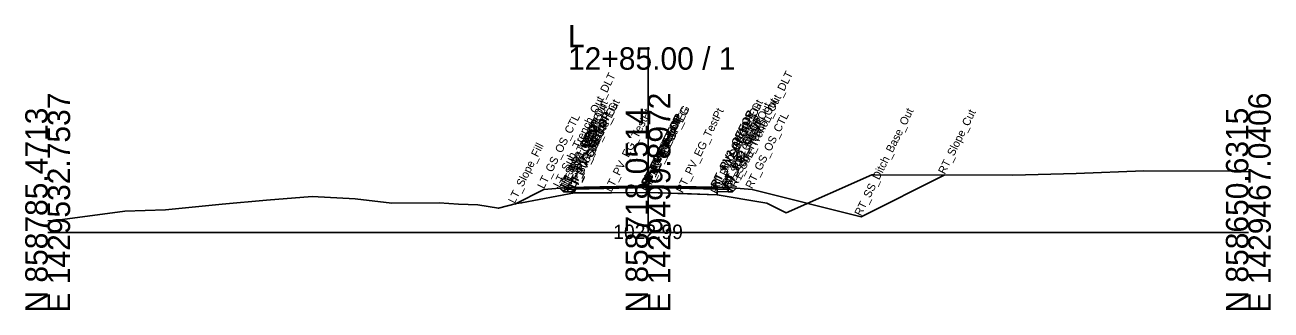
# Model space of a CAD drawing. Extents: x -26 to 2303, y -10 to 19558.
# Drawn here: x 1147.2 to 1302.8, y 4990.3 to 5025.9 of the extents above; entities that cross this region are included whole.
import ezdxf

# ---------------------------------------------------------------- set-up
doc = ezdxf.new("R2010")
doc.units = 0
for name, color, linetype in [('Default', 7, 'Continuous'), ('Exist CMT Pavement', 7, 'Continuous'), ('Exist Cross Section Cell', 7, 'Continuous'), ('Exist XS Center Line Elevation Label', 7, 'Continuous'), ('Exist XS Ground Line', 7, 'Continuous'), ('Prop CMT Conc Surface', 7, 'Continuous'), ('Prop CMT Pvmt Course 1', 7, 'Continuous'), ('Prop CMT Pvmt Course 1 Wedge', 7, 'Continuous'), ('Prop CMT Pvmt Course 2', 7, 'Continuous'), ('Prop CMT Pvmt Course 2 Wedge', 7, 'Continuous'), ('Prop CMT Pvmt Surface', 7, 'Continuous'), ('Prop CMT Pvmt Surface Shoulder', 7, 'Continuous'), ('Prop CMT Pvmt Wedge Surface 1', 7, 'Continuous'), ('Prop CMT Pvmt Wedge Surface 2', 7, 'Continuous'), ('Prop CMT Shld Paved Course 1', 7, 'Continuous'), ('Prop CMT Shld Paved Course 2', 7, 'Continuous'), ('Prop CMT Slope Grass', 7, 'Continuous'), ('Prop CMT Subgrade Earthwork', 7, 'Continuous'), ('Prop XS Dump Level', 7, 'Continuous')]:
    doc.layers.add(name, color=color, linetype=linetype)

msp = doc.modelspace()

# ---------------------------------------------------------------- linework, layer by layer
at = {"layer": 'Exist CMT Pavement'}
for points in [[(1225, 5004.99), (1215.83, 5004.95)], [(1215.83, 5004.95), (1220.42, 5004.98)], [(1220.42, 5004.98), (1225, 5004.99)], [(1229.33, 5004.86), (1225, 5004.99)], [(1225, 5004.99), (1233.66, 5004.72)], [(1233.66, 5004.72), (1229.33, 5004.86)]]:
    msp.add_lwpolyline(points, dxfattribs=at)
at = {"layer": 'Exist Cross Section Cell'}
for p, q in [((1225, 5000), (1225, 5023.15)), ((1150, 5000), (1225, 5000)), ((1225, 5000), (1300, 5000))]:
    msp.add_line(p, q, dxfattribs=at)
at = {"layer": 'Exist XS Ground Line'}
msp.add_lwpolyline([(1150, 5001.48), (1151.22, 5001.54), (1159.64, 5002.66), (1164.71, 5002.84), (1171.81, 5003.54), (1177.34, 5004.03), (1183.06, 5004.5), (1188.4, 5004.23), (1193, 5003.66), (1198.9, 5003.71), (1201.31, 5003.56), (1203.74, 5003.48), (1206.31, 5003.03), (1208.56, 5003.62), (1209.21, 5003.7), (1215.83, 5004.95), (1220.21, 5004.97), (1224.69, 5005), (1225, 5004.99), (1229.19, 5004.86), (1233.66, 5004.72), (1239.36, 5003.77), (1239.84, 5003.69), (1240.16, 5003.5), (1242.28, 5002.48), (1252.96, 5007.21), (1253.34, 5007.23), (1270.59, 5007.19), (1278.49, 5007.37), (1286.93, 5007.72), (1298.54, 5007.65), (1300, 5007.59)], dxfattribs=at)
at = {"layer": 'Prop CMT Conc Surface'}
for p, q in [((1215.83, 5005.1), (1215.83, 5004.95)), ((1233.66, 5004.72), (1233.66, 5005.11))]:
    msp.add_line(p, q, dxfattribs=at)
at = {"layer": 'Prop CMT Pvmt Course 1'}
for points in [[(1225, 5005.83), (1215, 5005.63)], [(1215, 5005.63), (1215, 5005.42)], [(1215, 5005.42), (1215.83, 5005.43)], [(1215.83, 5005.52), (1225, 5005.7)], [(1215.83, 5005.43), (1215.83, 5005.52)], [(1225, 5005.62), (1225, 5005.83)], [(1225, 5005.83), (1235, 5005.63)], [(1225, 5005.62), (1225, 5005.83)], [(1225, 5005.7), (1225, 5005.62), (1225, 5005.62)], [(1233.66, 5005.53), (1225, 5005.7)], [(1225, 5005.7), (1225, 5005.62), (1225, 5005.62)], [(1233.66, 5005.44), (1233.66, 5005.53)], [(1235, 5005.42), (1233.66, 5005.44)], [(1235, 5005.63), (1235, 5005.42)]]:
    msp.add_lwpolyline(points, dxfattribs=at)
at = {"layer": 'Prop CMT Pvmt Course 1 Wedge'}
for points in [[(1225, 5005.7), (1215.83, 5005.52)], [(1225, 5005.7), (1233.66, 5005.53)]]:
    msp.add_lwpolyline(points, dxfattribs=at)
at = {"layer": 'Prop CMT Pvmt Course 2'}
for points in [[(1215.83, 5005.43), (1215, 5005.42)], [(1215, 5005.42), (1215, 5005.08)], [(1215.83, 5005.1), (1215.83, 5005.43)], [(1233.66, 5005.11), (1233.66, 5005.44)], [(1233.66, 5005.44), (1235, 5005.42)], [(1235, 5005.42), (1235, 5005.08)], [(1215, 5005.08), (1215.83, 5005.1)], [(1235, 5005.08), (1233.66, 5005.11)]]:
    msp.add_lwpolyline(points, dxfattribs=at)
at = {"layer": 'Prop CMT Pvmt Course 2 Wedge'}
for points in [[(1225, 5005.62), (1215.83, 5005.43)], [(1225, 5005.62), (1233.66, 5005.44)]]:
    msp.add_lwpolyline(points, dxfattribs=at)
at = {"layer": 'Prop CMT Pvmt Surface'}
for points in [[(1225, 5005.83), (1215, 5005.63)], [(1225, 5005.83), (1235, 5005.63)]]:
    msp.add_lwpolyline(points, dxfattribs=at)
at = {"layer": 'Prop CMT Pvmt Surface Shoulder'}
for points in [[(1215, 5005.63), (1215, 5005.63)], [(1235, 5005.63), (1235, 5005.63)]]:
    msp.add_lwpolyline(points, dxfattribs=at)
at = {"layer": 'Prop CMT Pvmt Wedge Surface 1'}
for points in [[(1215, 5005.42), (1215, 5005.63)], [(1215.83, 5005.43), (1215, 5005.42)], [(1225, 5005.7), (1215.83, 5005.52)], [(1215.83, 5005.52), (1215.83, 5005.43)], [(1225, 5005.7), (1233.66, 5005.53)], [(1233.66, 5005.53), (1233.66, 5005.44)], [(1233.66, 5005.44), (1235, 5005.42)], [(1235, 5005.42), (1235, 5005.63)]]:
    msp.add_lwpolyline(points, dxfattribs=at)
at = {"layer": 'Prop CMT Pvmt Wedge Surface 2'}
for points in [[(1215, 5005.42), (1215, 5005.63)], [(1225, 5005.62), (1215, 5005.42)], [(1225, 5005.62), (1235, 5005.42)], [(1235, 5005.42), (1235, 5005.63)]]:
    msp.add_lwpolyline(points, dxfattribs=at)
at = {"layer": 'Prop CMT Shld Paved Course 1'}
for points in [[(1215, 5005.63), (1214.79, 5005.41)], [(1214.79, 5005.41), (1215, 5005.42)], [(1215, 5005.63), (1215, 5005.63)], [(1215, 5005.42), (1215, 5005.63)], [(1235, 5005.63), (1235, 5005.63)], [(1235, 5005.63), (1235.21, 5005.41)], [(1235, 5005.42), (1235, 5005.63)], [(1235.21, 5005.41), (1235, 5005.42)]]:
    msp.add_lwpolyline(points, dxfattribs=at)
at = {"layer": 'Prop CMT Shld Paved Course 2'}
for points in [[(1214.79, 5005.41), (1214.45, 5005.07)], [(1215, 5005.42), (1214.79, 5005.41)], [(1214.79, 5005.41), (1214.79, 5005.41)], [(1215, 5005.08), (1215, 5005.42)], [(1235, 5005.42), (1235.21, 5005.41)], [(1235, 5005.08), (1235, 5005.42)], [(1235.21, 5005.41), (1235.21, 5005.41)], [(1235.21, 5005.41), (1235.55, 5005.07)], [(1214.45, 5005.07), (1215, 5005.08)], [(1235.55, 5005.07), (1235, 5005.08)]]:
    msp.add_lwpolyline(points, dxfattribs=at)
at = {"layer": 'Prop CMT Slope Grass'}
for points in [[(1235, 5005.63), (1238, 5005.39), (1251.62, 5001.98), (1262.08, 5007.21)], [(1215, 5005.63), (1212, 5005.39), (1208.35, 5003.56)]]:
    msp.add_lwpolyline(points, dxfattribs=at)
at = {"layer": 'Prop CMT Subgrade Earthwork'}
for points in [[(1214.45, 5005.07), (1213.98, 5005.54)], [(1235.55, 5005.07), (1236.02, 5005.54)], [(1215, 5005.08), (1214.45, 5005.07)], [(1215.83, 5005.1), (1215, 5005.08)], [(1215.83, 5005.1), (1215.85, 5004.95)], [(1233.66, 5005.11), (1233.65, 5004.72)], [(1233.66, 5005.11), (1235, 5005.08)], [(1235, 5005.08), (1235.55, 5005.07)]]:
    msp.add_lwpolyline(points, dxfattribs=at)

# ---------------------------------------------------------------- texts
at = {"layer": 'Default'}
msp.add_text('-', height=0.0001, dxfattribs=at).set_placement((1150, 5000))
at = {"layer": 'Exist Cross Section Cell'}
for s, p in [('L', (1215, 5023.15)), ('12+85.00 / 1', (1215, 5020.35))]:
    msp.add_text(s, height=2.8, dxfattribs=at).set_placement(p)
for s, p in [('E 1429532.7537', (1152.8, 4990)), ('E 1429499.8972', (1227.8, 4990)), ('E 1429467.0406', (1302.8, 4990)), ('N 858785.4713', (1150, 4990)), ('N 858718.0514', (1225, 4990)), ('N 858650.6315', (1300, 4990))]:
    msp.add_text(s, height=2.8, rotation=90, dxfattribs=at).set_placement(p)
at = {"layer": 'Exist XS Center Line Elevation Label'}
msp.add_text('1022.99', height=1.8, dxfattribs=at).set_placement((1220.66, 4999.19))
at = {"layer": 'Prop XS Dump Level'}
for s, p in [('LT_Sub_Trench_Out_DLT', (1213.98, 5005.54)), ('RT_Sub_Trench_Out_DLT', (1236.02, 5005.54)), ('LT_Sub_Trench_Out', (1214.45, 5005.07)), ('LT_PV_OEEOP_EG', (1215.83, 5004.95)), ('LT_PV_Sub_Tie_Out', (1215.85, 5004.95)), ('RT_PV_Sub_Tie_Out', (1233.65, 5004.72)), ('RT_PV_OEEOP_EG', (1233.66, 5004.72)), ('RT_PS2_Shelf_Out', (1235.21, 5005.41)), ('RT_Sub_Trench_Out', (1235.55, 5005.07)), ('LT_GS_OS_CTL', (1212, 5005.39)), ('LT_PS2_Shelf_Out', (1214.79, 5005.41)), ('LT_PV1_OEEOP', (1215.83, 5005.52)), ('LT_PV2_OEEOP', (1215.83, 5005.43)), ('LT_Sub_OEEOP', (1215.83, 5005.1)), ('LT_PV_EG_TestPt', (1220.42, 5004.98)), ('RT_PV_IEEOP_EG', (1225, 5004.99)), ('LT_PV_IEEOP_EG', (1225, 5004.99)), ('RT_PV1_IEEOP', (1225, 5005.7)), ('RT_PV2_IEEOP', (1225, 5005.62)), ('LT_PV1_IEEOP', (1225, 5005.7)), ('LT_PV2_IEEOP', (1225, 5005.62)), ('RT_PV_EG_TestPt', (1229.33, 5004.86)), ('RT_PV1_OEEOP', (1233.66, 5005.53)), ('RT_PV2_OEEOP', (1233.66, 5005.44)), ('RT_Sub_OEEOP', (1233.66, 5005.11)), ('RT_PV1_OEOT', (1235, 5005.63)), ('RT_PS1_OEOP', (1235, 5005.63)), ('RT_GS_OS_CTL', (1238, 5005.39)), ('RT_SS_Ditch_Base_Out', (1251.62, 5001.98)), ('RT_Slope_Cut', (1262.08, 5007.21)), ('LT_PS2_OEOP', (1214.79, 5005.41)), ('LT_PV1_OEOT', (1215, 5005.63)), ('LT_PS1_OEOP', (1215, 5005.63)), ('LT_PV2_OEOT', (1215, 5005.42)), ('LT_Sub_OEOT', (1215, 5005.08)), ('RT_PV2_OEOT', (1235, 5005.42)), ('RT_Sub_OEOT', (1235, 5005.08)), ('RT_PS2_OEOP', (1235.21, 5005.41)), ('LT_Slope_Fill', (1208.35, 5003.56)), ('PV1_PGL', (1225, 5005.83)), ('PV2_PGL', (1225, 5005.62))]:
    msp.add_text(s, height=1, rotation=63.5833, dxfattribs=at).set_placement(p)

doc.saveas('drawing.dxf')
